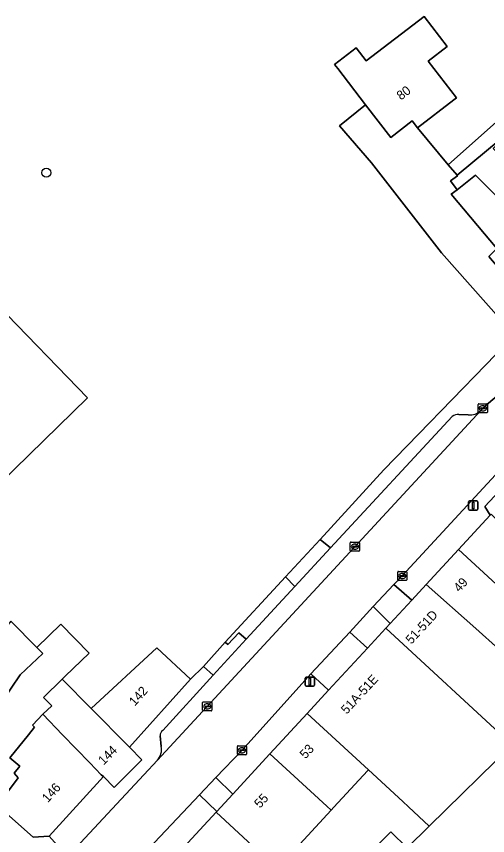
# Model space of a CAD drawing. Extents: x 161771 to 163125, y 382475 to 383179.
# Drawn here: x 162011.1 to 162062.6, y 382779.9 to 382869.5 of the extents above; entities that cross this region are included whole.
import ezdxf

# ---------------------------------------------------------------- set-up
doc = ezdxf.new("R2010")
doc.units = 0
for name, color, linetype in [('IMGEO_Boom', 7, 'Continuous'), ('IMGEO_Erf', 7, 'Continuous'), ('IMGEO_Kolk', 7, 'Continuous'), ('IMGEO_Lichtmast', 7, 'Continuous'), ('IMGEO_Muur', 7, 'Continuous'), ('IMGEO_Pand', 7, 'Continuous'), ('IMGEO_Pand_nummerreeks', 7, 'Continuous'), ('IMGEO_Parkeervlak_open', 7, 'Continuous'), ('IMGEO_Rijbaan_lokaal_open', 7, 'Continuous'), ('IMGEO_Voetpad_open', 7, 'Continuous')]:
    doc.layers.add(name, color=color, linetype=linetype)

msp = doc.modelspace()

# ---------------------------------------------------------------- linework, layer by layer
at = {"layer": 'IMGEO_Boom'}
msp.add_circle((162014.374, 382852.42), 0.489, dxfattribs=at)
at = {"layer": 'IMGEO_Erf'}
for points in [[(162010.483, 382803.357), (162013.343, 382800.477), (162015.975, 382803.035), (162019.062, 382799.858), (162016.459, 382797.328), (162016.114, 382796.992), (162019.285, 382793.772), (162026.472, 382800.423), (162030.133, 382797.017), (162031.577, 382798.403), (162033.948, 382801.058), (162040.546, 382808.213), (162044.337, 382812.289), (162051.316, 382819.905), (162055.097, 382823.809), (162058.778, 382827.609), (162062.458, 382831.409), (162065.602, 382834.655), (162057.62, 382843.655), (162049.956, 382853.511), (162046.448, 382857.555), (162049.31, 382859.864), (162046.262, 382863.828), (162045.914, 382864.279), (162048.271, 382866.092), (162049.377, 382864.654), (162055.694, 382869.529), (162058.229, 382866.239), (162056.14, 382864.632), (162059.24, 382860.603), (162058.955, 382860.384), (162054.992, 382857.335), (162058.342, 382853.296), (162075.47, 382868.534)], [(162008.957, 382837.998), (162018.897, 382827.792), (162002.91, 382812.221)]]:
    msp.add_lwpolyline(points, dxfattribs=at)
for points in [[(162064.598, 382853.695), (162063.247, 382855.061), (162065.398, 382857.189), (162065.515, 382857.305), (162059.305, 382852.135), (162059.352, 382852.078), (162058.578, 382851.531), (162059.301, 382850.566), (162061.338, 382852.148), (162066.501, 382846.927), (162067.582, 382847.995), (162068.923, 382849.322)], [(162050.121, 382778.345), (162052.075, 382780.302), (162053.843, 382778.537), (162056.273, 382780.922), (162053.978, 382783.039), (162053.372, 382783.599), (162049.612, 382787.069), (162049.511, 382786.96), (162045.834, 382782.975), (162045.541, 382782.658), (162041.272, 382778.032), (162041.112, 382778.18), (162039.481, 382776.414), (162036.886, 382778.809), (162032.434, 382773.985), (162036.827, 382769.931), (162036.907, 382769.857), (162037.06, 382770.023), (162043.885, 382777.305), (162045.61, 382777.374), (162047.796, 382775.356), (162049.242, 382774.021), (162050.306, 382775.065), (162051.869, 382776.599)]]:
    msp.add_lwpolyline(points, close=True, dxfattribs=at)
at = {"layer": 'IMGEO_Kolk'}
for p, q in [((162061.626, 382826.216), (162061.626, 382827.068)), ((162061.701, 382827.142), (162062.553, 382827.142)), ((162062.627, 382827.068), (162062.627, 382826.216)), ((162062.553, 382826.142), (162061.701, 382826.142)), ((162061.885, 382826.636), (162061.885, 382826.648)), ((162062.323, 382826.599), (162061.925, 382826.599)), ((162061.928, 382826.685), (162062.326, 382826.685)), ((162062.137, 382826.362), (162062.112, 382826.362)), ((162062.114, 382826.922), (162062.139, 382826.922)), ((162062.369, 382826.648), (162062.369, 382826.636)), ((162047.632, 382811.077), (162047.632, 382811.929)), ((162047.707, 382812.003), (162048.559, 382812.003)), ((162048.12, 382811.783), (162048.145, 382811.783)), ((162048.633, 382811.929), (162048.633, 382811.077)), ((162048.559, 382811.003), (162047.707, 382811.003)), ((162047.891, 382811.497), (162047.891, 382811.509)), ((162048.329, 382811.46), (162047.931, 382811.46)), ((162047.934, 382811.546), (162048.332, 382811.546)), ((162048.143, 382811.223), (162048.118, 382811.223)), ((162048.375, 382811.509), (162048.375, 382811.497)), ((162052.816, 382807.868), (162052.816, 382808.72)), ((162052.891, 382808.794), (162053.743, 382808.794)), ((162053.075, 382808.288), (162053.075, 382808.3)), ((162053.513, 382808.251), (162053.115, 382808.251)), ((162053.118, 382808.337), (162053.516, 382808.337)), ((162053.304, 382808.574), (162053.329, 382808.574)), ((162053.559, 382808.3), (162053.559, 382808.288)), ((162053.817, 382808.72), (162053.817, 382807.868)), ((162053.743, 382807.794), (162052.891, 382807.794)), ((162053.327, 382808.014), (162053.302, 382808.014)), ((162031.479, 382793.594), (162031.479, 382794.446)), ((162031.554, 382794.52), (162032.406, 382794.52)), ((162031.738, 382794.014), (162031.738, 382794.026)), ((162032.176, 382793.977), (162031.778, 382793.977)), ((162031.781, 382794.063), (162032.179, 382794.063)), ((162031.967, 382794.3), (162031.992, 382794.3)), ((162032.222, 382794.026), (162032.222, 382794.014)), ((162032.48, 382794.446), (162032.48, 382793.594)), ((162032.406, 382793.52), (162031.554, 382793.52)), ((162031.99, 382793.74), (162031.965, 382793.74)), ((162035.28, 382788.793), (162035.28, 382789.645)), ((162035.355, 382789.719), (162036.207, 382789.719)), ((162035.768, 382789.499), (162035.793, 382789.499)), ((162036.281, 382789.645), (162036.281, 382788.793)), ((162036.207, 382788.719), (162035.355, 382788.719)), ((162035.539, 382789.213), (162035.539, 382789.225)), ((162035.977, 382789.176), (162035.579, 382789.176)), ((162035.582, 382789.262), (162035.98, 382789.262)), ((162035.791, 382788.939), (162035.766, 382788.939)), ((162036.023, 382789.225), (162036.023, 382789.213))]:
    msp.add_line(p, q, dxfattribs=at)
for points in [[(162061.626, 382826.216), (162061.626, 382827.068)], [(162061.701, 382827.142), (162062.553, 382827.142)], [(162062.627, 382827.068), (162062.627, 382826.216)], [(162062.553, 382826.142), (162061.701, 382826.142)], [(162047.632, 382811.077), (162047.632, 382811.929)], [(162047.707, 382812.003), (162048.559, 382812.003)], [(162048.633, 382811.929), (162048.633, 382811.077)], [(162048.559, 382811.003), (162047.707, 382811.003)], [(162052.816, 382807.868), (162052.816, 382808.72)], [(162052.891, 382808.794), (162053.743, 382808.794)], [(162053.817, 382808.72), (162053.817, 382807.868)], [(162053.743, 382807.794), (162052.891, 382807.794)], [(162031.479, 382793.594), (162031.479, 382794.446)], [(162031.554, 382794.52), (162032.406, 382794.52)], [(162032.48, 382794.446), (162032.48, 382793.594)], [(162032.406, 382793.52), (162031.554, 382793.52)], [(162035.28, 382788.793), (162035.28, 382789.645)], [(162035.355, 382789.719), (162036.207, 382789.719)], [(162036.281, 382789.645), (162036.281, 382788.793)], [(162036.207, 382788.719), (162035.355, 382788.719)]]:
    msp.add_lwpolyline(points, dxfattribs=at)
for centre, radius, start, end in [((162061.703, 382827.066), 0.0765, 91.55205, 178.44795), ((162061.703, 382827.066), 0.0765, 91.55205, 178.44795), ((162062.551, 382827.066), 0.0765, 1.55205, 88.44795), ((162062.551, 382827.066), 0.0765, 1.55205, 88.44795), ((162061.703, 382826.218), 0.0765, 181.55205, 268.44795), ((162061.703, 382826.218), 0.0765, 181.55205, 268.44795), ((162061.925, 382826.645), 0.0403, 85.87752, 175.75265), ((162061.922, 382826.635), 0.0366, 178.93798, 274.71019), ((162062.326, 382826.642), 0.043, 264.86636, 352.45326), ((162062.33, 382826.647), 0.0386, 1.73085, 96.63898), ((162062.551, 382826.218), 0.0765, 271.55205, 358.44795), ((162062.551, 382826.218), 0.0765, 271.55205, 358.44795), ((162047.709, 382811.927), 0.0765, 91.55205, 178.44795), ((162047.709, 382811.927), 0.0765, 91.55205, 178.44795), ((162048.557, 382811.927), 0.0765, 1.55205, 88.44795), ((162048.557, 382811.927), 0.0765, 1.55205, 88.44795), ((162047.709, 382811.079), 0.0765, 181.55205, 268.44795), ((162047.709, 382811.079), 0.0765, 181.55205, 268.44795), ((162047.931, 382811.506), 0.0403, 85.87752, 175.75265), ((162047.928, 382811.496), 0.0366, 178.93798, 274.71019), ((162048.332, 382811.503), 0.043, 264.86636, 352.45326), ((162048.336, 382811.508), 0.0386, 1.73085, 96.63898), ((162048.557, 382811.079), 0.0765, 271.55205, 358.44795), ((162048.557, 382811.079), 0.0765, 271.55205, 358.44795), ((162052.893, 382808.718), 0.0765, 91.55205, 178.44795), ((162052.893, 382808.718), 0.0765, 91.55205, 178.44795), ((162053.115, 382808.297), 0.0403, 85.87752, 175.75265), ((162053.112, 382808.287), 0.0366, 178.93798, 274.71019), ((162053.516, 382808.294), 0.043, 264.86636, 352.45326), ((162053.52, 382808.299), 0.0386, 1.73085, 96.63898), ((162053.741, 382808.718), 0.0765, 1.55205, 88.44795), ((162053.741, 382808.718), 0.0765, 1.55205, 88.44795), ((162052.893, 382807.87), 0.0765, 181.55205, 268.44795), ((162052.893, 382807.87), 0.0765, 181.55205, 268.44795), ((162053.741, 382807.87), 0.0765, 271.55205, 358.44795), ((162053.741, 382807.87), 0.0765, 271.55205, 358.44795), ((162031.556, 382794.444), 0.0765, 91.55205, 178.44795), ((162031.556, 382794.444), 0.0765, 91.55205, 178.44795), ((162031.778, 382794.023), 0.0403, 85.87752, 175.75265), ((162031.775, 382794.013), 0.0366, 178.93798, 274.71019), ((162032.179, 382794.02), 0.043, 264.86636, 352.45326), ((162032.183, 382794.025), 0.0386, 1.73085, 96.63898), ((162032.404, 382794.444), 0.0765, 1.55205, 88.44795), ((162032.404, 382794.444), 0.0765, 1.55205, 88.44795), ((162031.556, 382793.596), 0.0765, 181.55205, 268.44795), ((162031.556, 382793.596), 0.0765, 181.55205, 268.44795), ((162032.404, 382793.596), 0.0765, 271.55205, 358.44795), ((162032.404, 382793.596), 0.0765, 271.55205, 358.44795), ((162035.357, 382789.643), 0.0765, 91.55205, 178.44795), ((162035.357, 382789.643), 0.0765, 91.55205, 178.44795), ((162036.205, 382789.643), 0.0765, 1.55205, 88.44795), ((162036.205, 382789.643), 0.0765, 1.55205, 88.44795), ((162035.357, 382788.795), 0.0765, 181.55205, 268.44795), ((162035.357, 382788.795), 0.0765, 181.55205, 268.44795), ((162035.579, 382789.222), 0.0403, 85.87752, 175.75265), ((162035.576, 382789.212), 0.0366, 178.93798, 274.71019), ((162035.98, 382789.219), 0.043, 264.86636, 352.45326), ((162035.984, 382789.224), 0.0386, 1.73085, 96.63898), ((162036.205, 382788.795), 0.0765, 271.55205, 358.44795), ((162036.205, 382788.795), 0.0765, 271.55205, 358.44795)]:
    msp.add_arc(centre, radius, start, end, dxfattribs=at)
for centre, major_axis, ratio, start_param, end_param in [((162062.113, 382826.642), (-0.387, 0.002), 0.722429, 4.712389, 7.853982), ((162062.138, 382826.642), (-0.39, 0.002), 0.717154, 1.570796, 4.712389), ((162048.119, 382811.503), (-0.387, 0.002), 0.722429, 4.712389, 7.853982), ((162048.144, 382811.503), (-0.39, 0.002), 0.717154, 1.570796, 4.712389), ((162053.303, 382808.294), (-0.387, 0.002), 0.722429, 4.712389, 7.853982), ((162053.328, 382808.294), (-0.39, 0.002), 0.717154, 1.570796, 4.712389), ((162031.966, 382794.02), (-0.387, 0.002), 0.722429, 4.712389, 7.853982), ((162031.991, 382794.02), (-0.39, 0.002), 0.717154, 1.570796, 4.712389), ((162035.767, 382789.219), (-0.387, 0.002), 0.722429, 4.712389, 7.853982), ((162035.792, 382789.219), (-0.39, 0.002), 0.717154, 1.570796, 4.712389)]:
    msp.add_ellipse(centre, major_axis=major_axis, ratio=ratio, start_param=start_param, end_param=end_param, dxfattribs=at)
at = {"layer": 'IMGEO_Lichtmast'}
for p, q in [((162060.576, 382815.611), (162060.576, 382816.411)), ((162060.576, 382816.411), (162060.576, 382815.611)), ((162060.676, 382816.511), (162061.466, 382816.511)), ((162061.466, 382816.511), (162060.676, 382816.511)), ((162061.566, 382816.411), (162061.566, 382815.611)), ((162061.566, 382815.611), (162061.566, 382816.411)), ((162061.466, 382815.511), (162060.676, 382815.511)), ((162060.676, 382815.511), (162061.466, 382815.511)), ((162042.708, 382796.326), (162042.708, 382797.126)), ((162042.708, 382797.126), (162042.708, 382796.326)), ((162042.808, 382797.226), (162043.598, 382797.226)), ((162043.598, 382797.226), (162042.808, 382797.226)), ((162043.698, 382797.126), (162043.698, 382796.326)), ((162043.698, 382796.326), (162043.698, 382797.126)), ((162043.598, 382796.226), (162042.808, 382796.226)), ((162042.808, 382796.226), (162043.598, 382796.226))]:
    msp.add_line(p, q, dxfattribs=at)
for points in [[(162060.996, 382816.386), (162061.146, 382816.386), (162061.146, 382815.636), (162060.996, 382815.636), (162060.996, 382816.386)], [(162043.128, 382797.101), (162043.278, 382797.101), (162043.278, 382796.351), (162043.128, 382796.351), (162043.128, 382797.101)]]:
    msp.add_lwpolyline(points, dxfattribs=at)
for centre, start, end in [((162060.676, 382816.411), 90, 180), ((162060.676, 382816.411), 90, 180), ((162061.466, 382816.411), 0, 90), ((162061.466, 382816.411), 360, 90), ((162060.676, 382815.611), 180, 270), ((162060.676, 382815.611), 180, 270), ((162061.466, 382815.611), 270, 0), ((162061.466, 382815.611), 270, 0), ((162042.808, 382797.126), 90, 180), ((162042.808, 382797.126), 90, 180), ((162043.598, 382797.126), 0, 90), ((162043.598, 382797.126), 360, 90), ((162042.808, 382796.326), 180, 270), ((162042.808, 382796.326), 180, 270), ((162043.598, 382796.326), 270, 0), ((162043.598, 382796.326), 270, 0)]:
    msp.add_arc(centre, 0.1, start, end, dxfattribs=at)
at = {"layer": 'IMGEO_Muur'}
msp.add_lwpolyline([(162030.133, 382797.017), (162031.577, 382798.403)], dxfattribs=at)
at = {"layer": 'IMGEO_Pand'}
for points in [[(162049.31, 382859.864), (162052.063, 382856.285), (162054.411, 382858.09), (162054.992, 382857.335), (162058.955, 382860.384), (162059.24, 382860.603), (162056.14, 382864.632), (162058.229, 382866.239), (162055.694, 382869.529), (162049.377, 382864.654), (162048.271, 382866.092), (162045.914, 382864.279), (162046.262, 382863.828)], [(162067.582, 382847.995), (162066.501, 382846.927), (162061.338, 382852.148), (162059.301, 382850.566), (162058.654, 382850.064), (162063.668, 382844.124), (162062.776, 382843.242), (162067.09, 382838.181), (162069.123, 382838.17), (162073.253, 382842.261)], [(162059.463, 382811.187), (162070.497, 382801.002), (162073.135, 382798.566), (162076.169, 382801.854), (162073.532, 382804.289), (162072.186, 382802.831), (162070.765, 382804.244), (162066.794, 382808.192), (162068.324, 382809.851), (162063.036, 382815.058), (162062.919, 382814.932)], [(162059.463, 382811.187), (162055.945, 382807.375), (162061.372, 382802.535), (162063.892, 382800.286), (162065.548, 382802.081), (162067.287, 382800.476), (162068.758, 382799.118), (162070.497, 382801.002)], [(162063.892, 382800.286), (162061.372, 382802.535), (162055.945, 382807.375), (162054.352, 382805.649), (162051.986, 382803.085), (162051.522, 382802.582), (162065.345, 382789.825), (162070.236, 382794.626)], [(162011.528, 382797.48), (162014.005, 382799.81), (162013.343, 382800.477), (162010.483, 382803.357), (162008.976, 382801.465), (162005.777, 382797.449), (162004.747, 382798.281), (162002.233, 382795.15), (162000, 382792.399), (161999.165, 382791.37), (161997.776, 382789.66), (162000, 382787.854), (162003.337, 382785.143), (162007.703, 382790.52), (162006.847, 382791.215), (162009.56, 382794.557)], [(162014.006, 382793.154), (162014.966, 382794.089), (162014.073, 382795.007), (162016.114, 382796.992), (162016.459, 382797.328), (162019.062, 382799.858), (162015.975, 382803.035), (162013.343, 382800.477), (162014.005, 382799.81), (162011.528, 382797.48), (162009.56, 382794.557), (162006.847, 382791.215), (162007.703, 382790.52), (162003.337, 382785.143), (162007.486, 382781.832), (162008.9, 382783.259), (162008.994, 382783.177), (162011.304, 382786.195), (162010.863, 382786.72), (162011.481, 382787.481), (162010.376, 382788.379), (162012.441, 382790.923), (162013.088, 382791.763), (162012.855, 382791.952)], [(162051.522, 382802.582), (162049.509, 382800.4), (162045.244, 382795.779), (162042.912, 382793.253), (162049.612, 382787.069), (162053.372, 382783.599), (162053.978, 382783.039), (162056.273, 382780.922), (162065.345, 382789.825)], [(162019.285, 382793.772), (162023.32, 382789.695), (162023.468, 382789.545), (162030.133, 382797.017), (162026.472, 382800.423)], [(162019.285, 382793.772), (162016.114, 382796.992), (162014.073, 382795.007), (162014.966, 382794.089), (162014.006, 382793.154), (162016.154, 382790.92), (162019.129, 382787.826), (162020.385, 382786.52), (162020.641, 382786.362), (162021.798, 382785.144), (162024.841, 382788.163), (162023.468, 382789.545), (162023.32, 382789.695)], [(162076.682, 382791.573), (162071.683, 382796.187), (162070.236, 382794.626), (162065.345, 382789.825), (162056.273, 382780.922), (162053.843, 382778.537), (162051.869, 382776.599), (162050.306, 382775.065), (162049.242, 382774.021), (162045.101, 382769.956), (162045.846, 382769.268), (162036.24, 382758.865), (162041.234, 382754.251)], [(162019.129, 382787.826), (162016.154, 382790.92), (162014.006, 382793.154), (162012.855, 382791.952), (162013.088, 382791.763), (162012.441, 382790.923), (162010.376, 382788.379), (162011.481, 382787.481), (162010.863, 382786.72), (162011.304, 382786.195), (162008.994, 382783.177), (162012.95, 382779.713), (162014.703, 382779.815), (162020.641, 382786.362), (162020.385, 382786.52)], [(162049.511, 382786.96), (162049.612, 382787.069), (162042.912, 382793.253), (162038.842, 382788.842), (162045.071, 382783.092), (162045.541, 382782.658), (162045.834, 382782.975)], [(162045.541, 382782.658), (162045.071, 382783.092), (162038.842, 382788.842), (162034.773, 382784.433), (162033.019, 382782.533), (162032.943, 382782.45), (162036.886, 382778.809), (162039.481, 382776.414), (162041.112, 382778.18), (162041.272, 382778.032)], [(162036.886, 382778.809), (162032.943, 382782.45), (162022.711, 382771.363), (162026.169, 382768.169), (162031.95, 382774.432), (162032.434, 382773.985)], [(162053.843, 382778.537), (162052.075, 382780.302), (162050.121, 382778.345), (162051.869, 382776.599)]]:
    msp.add_lwpolyline(points, close=True, dxfattribs=at)
msp.add_lwpolyline([(162002.91, 382812.221), (162018.897, 382827.792), (162008.957, 382837.998)], dxfattribs=at)
at = {"layer": 'IMGEO_Parkeervlak_open'}
for points in [[(162026.538, 382788.136), (162061.907, 382826.409)], [(162058.771, 382825.758), (162045.469, 382811.365), (162041.56, 382807.135), (162036.238, 382801.376), (162032.62, 382797.429), (162027.119, 382791.397)], [(162060.538, 382825.942), (162059.499, 382825.97)], [(162026.848, 382790.79), (162026.943, 382789.638)]]:
    msp.add_lwpolyline(points, dxfattribs=at)
for centre, radius, start, end in [((162060.768, 382827.508), 1.583, 261.64917, 316.02241), ((162059.465, 382824.733), 1.238, 88.40319, 124.06886), ((162027.473, 382790.875), 0.631, 124.14069, 187.74181), ((162025.278, 382789.281), 1.703, 317.73426, 12.08499)]:
    msp.add_arc(centre, radius, start, end, dxfattribs=at)
at = {"layer": 'IMGEO_Rijbaan_lokaal_open'}
for points in [[(162058.654, 382850.064), (162059.301, 382850.566), (162058.578, 382851.531), (162059.352, 382852.078), (162059.305, 382852.135), (162058.342, 382853.296), (162054.992, 382857.335), (162054.411, 382858.09), (162052.063, 382856.285), (162049.31, 382859.864), (162046.448, 382857.555), (162049.956, 382853.511), (162057.62, 382843.655), (162065.602, 382834.655), (162066.249, 382835.323), (162069.123, 382838.17), (162067.09, 382838.181), (162062.776, 382843.242), (162063.668, 382844.124)], [(162050.138, 382804.936), (162052.396, 382807.356), (162053.317, 382808.296), (162066.601, 382822.699), (162066.75, 382822.87), (162071.513, 382828.84), (162074.309, 382831.578), (162071.188, 382834.811), (162067.689, 382831.412), (162062.286, 382826.805), (162061.907, 382826.409), (162026.538, 382788.136), (162025.06, 382786.542), (162017.123, 382778.034), (162016.666, 382777.602), (162020.985, 382773.585), (162021.432, 382774.044), (162025.583, 382778.478), (162031.126, 382784.345), (162032.929, 382786.229), (162035.793, 382789.231), (162043.321, 382797.573), (162047.591, 382802.152)]]:
    msp.add_lwpolyline(points, close=True, dxfattribs=at)
at = {"layer": 'IMGEO_Voetpad_open'}
for points in [[(162075.47, 382868.534), (162058.342, 382853.296), (162059.305, 382852.135), (162065.515, 382857.305), (162067.856, 382859.621), (162076.16, 382867.837)], [(162063.959, 382817.626), (162062.347, 382815.889), (162062.919, 382814.932), (162063.036, 382815.058), (162068.324, 382809.851), (162076.939, 382801.368), (162077.401, 382801.823), (162077.704, 382801.549), (162090.802, 382815.081), (162092.271, 382816.598), (162091.492, 382817.363), (162089.13, 382814.979), (162086.815, 382812.622), (162080.413, 382806.084), (162080.567, 382805.932), (162078.28, 382803.627), (162078.138, 382803.768), (162078.025, 382803.653), (162072.111, 382809.534)], [(162041.56, 382807.135), (162045.469, 382811.365), (162044.337, 382812.289), (162040.546, 382808.213)], [(162036.238, 382801.376), (162041.56, 382807.135), (162040.546, 382808.213), (162033.948, 382801.058), (162034.244, 382800.788), (162035.454, 382802.075)], [(162054.352, 382805.649), (162052.396, 382807.356), (162050.138, 382804.936), (162051.986, 382803.085)], [(162051.522, 382802.582), (162051.986, 382803.085), (162050.138, 382804.936), (162047.591, 382802.152), (162049.509, 382800.4)], [(162032.62, 382797.429), (162036.238, 382801.376), (162035.454, 382802.075), (162034.244, 382800.788), (162033.948, 382801.058), (162031.577, 382798.403)], [(162045.244, 382795.779), (162049.509, 382800.4), (162047.591, 382802.152), (162043.321, 382797.573)], [(162034.773, 382784.433), (162038.842, 382788.842), (162042.912, 382793.253), (162045.244, 382795.779), (162043.321, 382797.573), (162035.793, 382789.231), (162032.929, 382786.229)], [(162032.929, 382786.229), (162031.126, 382784.345), (162033.019, 382782.533), (162034.773, 382784.433)], [(162032.943, 382782.45), (162033.019, 382782.533), (162031.126, 382784.345), (162025.583, 382778.478), (162021.432, 382774.044), (162020.985, 382773.585), (162022.711, 382771.363)]]:
    msp.add_lwpolyline(points, close=True, dxfattribs=at)
for points in [[(162013.278, 382773.96), (162016.666, 382777.602), (162014.703, 382779.815), (162012.95, 382779.713), (162008.994, 382783.177), (162008.9, 382783.259), (162007.486, 382781.832), (162003.337, 382785.143), (162000, 382787.854), (161997.776, 382789.66), (161999.165, 382791.37), (161993.375, 382796.093), (161993.267, 382795.96), (161979.452, 382807.183), (161979.326, 382806.979), (161978.893, 382807.245), (161972.332, 382811.265), (161965.52, 382815.44), (161962.509, 382817.293), (161953.171, 382822.43), (161943.963, 382827.66), (161944.451, 382828.498), (161919.878, 382842.285)], [(162061.907, 382826.409), (162062.286, 382826.805), (162067.689, 382831.412), (162067.341, 382831.77), (162070.84, 382835.169), (162071.188, 382834.811), (162073.189, 382836.841)], [(162065.602, 382834.655), (162062.458, 382831.409), (162058.778, 382827.609), (162055.097, 382823.809), (162051.316, 382819.905), (162044.337, 382812.289), (162045.469, 382811.365), (162058.771, 382825.758)], [(162059.499, 382825.97), (162060.538, 382825.942)], [(162066.601, 382822.699), (162053.317, 382808.296), (162052.396, 382807.356), (162054.352, 382805.649), (162055.945, 382807.375), (162059.463, 382811.187), (162062.919, 382814.932), (162062.347, 382815.889), (162063.959, 382817.626)], [(162032.62, 382797.429), (162031.577, 382798.403), (162030.133, 382797.017), (162023.468, 382789.545), (162024.841, 382788.163), (162021.798, 382785.144), (162020.641, 382786.362), (162014.703, 382779.815), (162016.666, 382777.602), (162017.123, 382778.034), (162025.06, 382786.542), (162026.538, 382788.136)], [(162027.119, 382791.397), (162032.62, 382797.429)], [(162026.943, 382789.638), (162026.848, 382790.79)]]:
    msp.add_lwpolyline(points, dxfattribs=at)
for centre, radius, start, end in [((162060.768, 382827.508), 1.583, 261.64917, 316.02241), ((162059.465, 382824.733), 1.238, 88.40319, 124.06886), ((162027.473, 382790.875), 0.631, 124.14069, 187.74181), ((162025.278, 382789.281), 1.703, 317.73426, 12.08499)]:
    msp.add_arc(centre, radius, start, end, dxfattribs=at)

# ---------------------------------------------------------------- texts
at = {"layer": 'IMGEO_Pand_nummerreeks'}
for s, rotation, p in [('80', 37.5509, (162053.172, 382860.317)), ('49', 47.29767, (162059.554, 382806.45)), ('51-51D', 47.29767, (162054.304, 382800.761)), ('51A-51E', 47.29767, (162047.235, 382793.1)), ('142', 48.26576, (162024.061, 382793.994)), ('144', 44.96, (162020.644, 382787.542)), ('53', 47.3034, (162042.726, 382788.216)), ('146', 47.84198, (162014.539, 382783.424)), ('55', 47.29767, (162037.743, 382782.815))]:
    msp.add_text(s, height=1, rotation=rotation, dxfattribs=at).set_placement(p)

doc.saveas('drawing.dxf')
